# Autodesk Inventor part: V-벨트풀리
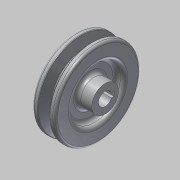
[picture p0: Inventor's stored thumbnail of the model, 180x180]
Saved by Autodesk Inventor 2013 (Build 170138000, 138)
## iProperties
Created: 2015-02
Part Number: V-벨트풀리
Material: 알루미늄 6061
Document SubType Name: Modeling
Designer: Administrator
Density: 2.71 g/cm^3
Mass: 131.415 g
Surface Area: 164.347 cm^2
Volume: 48.4928 cm^3
Author: Administrator
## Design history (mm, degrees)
sketch "스케치1"
  geometry: L1 (0, 0)-(25, 0); L2 (0, 5.5)-(25, 5.5); L3 (25, 5.5)-(25, 11); L4 (25, 11)-(13, 11); L5 (9.5, 0)-(9.5, 32.5); L6 (13, 11)-(13, 21.5); L7 (13, 21.5)-(19, 21.5); L8 (19, 21.5)-(19, 32.5); L9 (19, 32.5)-(19, 35.2); L10 (19, 35.2)-(14.325, 35.2); L11 (14.325, 35.2)-(13.5, 32.5); L12 (13.5, 32.5)-(11.574, 26.2); L13 (11.574, 26.2)-(9.5, 26.2); L14 (7.426, 26.2)-(9.5, 26.2); L15 (5.5, 32.5)-(7.426, 26.2); L16 (4.675, 35.2)-(5.5, 32.5); L17 (0, 35.2)-(4.675, 35.2); L18 (0, 32.5)-(0, 35.2); L19 (0, 21.5)-(0, 32.5); L20 (6, 21.5)-(0, 21.5); L21 (6, 11)-(6, 21.5); L22 (6, 11)-(0, 11); L23 (0, 11)-(0, 5.5); 3 further points
  constraints: 46 end point, 9 perpendicular, 8 symmetric about line, 3 midpoint, 3 vertical alignment, 2 collinear, 2 parallel, 2 point on line, 1 horizontal, 1 horizontal alignment
  dimensions: "d0" = 25 distance of L1.start L1.end; "d1" = 11 diameter of L2 L1; "d2" = 22 diameter of L4 L1; "d3" = 32.5 distance of L5.start L5.end; "d4" = 8 distance of L11.end L15.start; "d5" = 34 deg angle of L15 L12; "d6" = 19 distance between parallel lines of L19 L8; "d7" = 6 distance between parallel lines of L19 L21; "d8" = 43 diameter of L20 L1; "d9" = 2.7 distance from line of L10 L11.end; "d10" = 6.3 distance from line of L11.end L13
revolve "회전1" sketch "스케치1" stored, may be unused: angle "d11" = 90 deg
fillet "모깎기1" dims "d12" = 0.5, "d13" = 2, "d14" = 1
fillet "모깎기2" dims "d15" = 3
sketch "스케치2"
  geometry: L1 (-2, 0)-(2, 0); L2 (2, 0)-(2, 7.3); L3 (2, 7.3)-(-2, 7.3); L4 (-2, 7.3)-(-2, 0); C1 r 5.5 at (0, 0) reference; 1 further point
  constraints: 8 end point, 2 parallel, 1 coincident, 1 horizontal, 1 midpoint, 1 perpendicular
  dimensions: "d16" = 4 distance of L2.end L3.end; "d18" = 7.3 distance from line of L3 C1.centre
extrude "돌출1" cut sketch "스케치2" stored distance "d19" = 10; taper "d20" = 0 deg
node "솔리드1"
